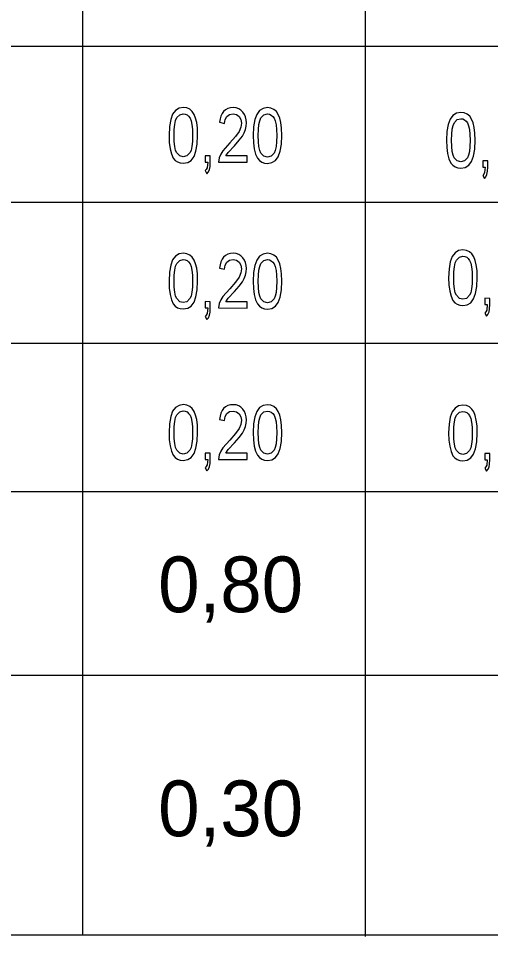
# Model space of a CAD drawing. Extents: x -480568.5 to -480543.1, y -1126945.4 to -1126930.6.
# Drawn here: x -480548.86 to -480548.039, y -1126935.262 to -1126933.667 of the extents above; entities that cross this region are included whole.
import ezdxf

# ---------------------------------------------------------------- set-up
doc = ezdxf.new("R2010")
doc.units = 0
doc.layers.add('detaily', color=7, linetype='Continuous')
doc.layers.add('EL1', color=7, linetype='Continuous')

msp = doc.modelspace()

# ---------------------------------------------------------------- linework, layer by layer
at = {"layer": 'detaily'}
msp.add_lwpolyline([(-480551.8459, -1126935.2592), (-480543.5956, -1126935.2592), (-480543.5956, -1126932.0257), (-480551.8459, -1126932.0257)], close=True, dxfattribs=at)
at = {"layer": 'EL1'}
for p, q in [((-480548.2567, -1126932.0257), (-480548.2567, -1126935.2623)), ((-480548.7479, -1126932.3271), (-480548.7479, -1126935.2592)), ((-480550.8407, -1126933.7155), (-480543.5956, -1126933.7155)), ((-480549.8036, -1126933.9862), (-480543.5956, -1126933.9862)), ((-480550.8351, -1126934.2311), (-480543.5956, -1126934.2311)), ((-480543.5956, -1126934.4894), (-480551.8459, -1126934.4894)), ((-480543.5956, -1126934.8085), (-480551.8459, -1126934.8085))]:
    msp.add_line(p, q, dxfattribs=at)
for points in [[(-480548.5976, -1126933.8705), (-480548.5972, -1126933.883), (-480548.5958, -1126933.8937), (-480548.5935, -1126933.9027), (-480548.5902, -1126933.91), (-480548.5868, -1126933.9139), (-480548.5827, -1126933.9166), (-480548.5781, -1126933.9183), (-480548.5729, -1126933.9189), (-480548.5652, -1126933.9176), (-480548.559, -1126933.9138), (-480548.5542, -1126933.9073), (-480548.5508, -1126933.8979), (-480548.5487, -1126933.8857), (-480548.548, -1126933.8705), (-480548.5484, -1126933.8579), (-480548.5496, -1126933.8481), (-480548.5516, -1126933.8405), (-480548.554, -1126933.834), (-480548.5572, -1126933.8289), (-480548.5616, -1126933.8251), (-480548.5669, -1126933.8228), (-480548.5727, -1126933.822), (-480548.5803, -1126933.8233), (-480548.5865, -1126933.8271), (-480548.5914, -1126933.8337), (-480548.5948, -1126933.8429), (-480548.5969, -1126933.8552)], [(-480548.4617, -1126933.9062), (-480548.4992, -1126933.9062), (-480548.4947, -1126933.9), (-480548.4836, -1126933.8883), (-480548.4755, -1126933.879), (-480548.4702, -1126933.8717), (-480548.4669, -1126933.8658), (-480548.4648, -1126933.8601), (-480548.4635, -1126933.8545), (-480548.4631, -1126933.8488), (-480548.4635, -1126933.8434), (-480548.4646, -1126933.8384), (-480548.4666, -1126933.8339), (-480548.4692, -1126933.8298), (-480548.4726, -1126933.8265), (-480548.4765, -1126933.8241), (-480548.481, -1126933.8226), (-480548.486, -1126933.8222), (-480548.491, -1126933.8226), (-480548.4954, -1126933.8238), (-480548.4993, -1126933.8259), (-480548.5027, -1126933.8287), (-480548.5055, -1126933.8324), (-480548.5076, -1126933.8368), (-480548.509, -1126933.8419), (-480548.5099, -1126933.8477), (-480548.5011, -1126933.8495), (-480548.5001, -1126933.8427), (-480548.497, -1126933.8375), (-480548.4923, -1126933.8342), (-480548.4862, -1126933.8331), (-480548.4804, -1126933.8343), (-480548.4758, -1126933.8378), (-480548.4729, -1126933.843), (-480548.4719, -1126933.8492), (-480548.4729, -1126933.8563), (-480548.4759, -1126933.8634), (-480548.4819, -1126933.8721), (-480548.4918, -1126933.8836), (-480548.5039, -1126933.8971), (-480548.5077, -1126933.903), (-480548.5103, -1126933.9092), (-480548.5114, -1126933.9171), (-480548.4617, -1126933.9172)], [(-480548.4514, -1126933.8706), (-480548.4509, -1126933.8831), (-480548.4495, -1126933.8939), (-480548.4472, -1126933.9029), (-480548.4439, -1126933.9101), (-480548.4405, -1126933.914), (-480548.4364, -1126933.9168), (-480548.4318, -1126933.9185), (-480548.4266, -1126933.919), (-480548.419, -1126933.9178), (-480548.4127, -1126933.9139), (-480548.4079, -1126933.9074), (-480548.4045, -1126933.8981), (-480548.4024, -1126933.8859), (-480548.4017, -1126933.8707), (-480548.4021, -1126933.8581), (-480548.4034, -1126933.8483), (-480548.4053, -1126933.8406), (-480548.4077, -1126933.8342), (-480548.4109, -1126933.8291), (-480548.4153, -1126933.8253), (-480548.4206, -1126933.823), (-480548.4265, -1126933.8222), (-480548.4341, -1126933.8235), (-480548.4403, -1126933.8273), (-480548.4451, -1126933.8339), (-480548.4485, -1126933.8431), (-480548.4507, -1126933.8554)], [(-480548.5889, -1126933.8704), (-480548.5886, -1126933.8601), (-480548.5877, -1126933.8515), (-480548.5862, -1126933.8447), (-480548.5841, -1126933.8396), (-480548.5791, -1126933.8347), (-480548.5729, -1126933.833), (-480548.5694, -1126933.8335), (-480548.5663, -1126933.8349), (-480548.5636, -1126933.8372), (-480548.5611, -1126933.8404), (-480548.5592, -1126933.8451), (-480548.5578, -1126933.8517), (-480548.557, -1126933.8602), (-480548.5567, -1126933.8705), (-480548.557, -1126933.8812), (-480548.5579, -1126933.8898), (-480548.5594, -1126933.8964), (-480548.5614, -1126933.9009), (-480548.5666, -1126933.9062), (-480548.5728, -1126933.9079), (-480548.5791, -1126933.9062), (-480548.5843, -1126933.9009), (-480548.5863, -1126933.8964), (-480548.5878, -1126933.8898), (-480548.5886, -1126933.8812)], [(-480548.4426, -1126933.8706), (-480548.4423, -1126933.8603), (-480548.4414, -1126933.8517), (-480548.4399, -1126933.8449), (-480548.4378, -1126933.8397), (-480548.4328, -1126933.8348), (-480548.4266, -1126933.8332), (-480548.4231, -1126933.8337), (-480548.42, -1126933.8351), (-480548.4173, -1126933.8374), (-480548.4149, -1126933.8406), (-480548.4129, -1126933.8453), (-480548.4115, -1126933.8519), (-480548.4107, -1126933.8603), (-480548.4104, -1126933.8707), (-480548.4107, -1126933.8814), (-480548.4116, -1126933.89), (-480548.4131, -1126933.8966), (-480548.4151, -1126933.9011), (-480548.4203, -1126933.9064), (-480548.4266, -1126933.9081), (-480548.4328, -1126933.9063), (-480548.438, -1126933.9011), (-480548.44, -1126933.8966), (-480548.4415, -1126933.89), (-480548.4423, -1126933.8814)], [(-480548.1153, -1126933.8789), (-480548.1148, -1126933.8914), (-480548.1134, -1126933.9021), (-480548.1111, -1126933.9112), (-480548.1078, -1126933.9184), (-480548.1044, -1126933.9223), (-480548.1003, -1126933.9251), (-480548.0957, -1126933.9267), (-480548.0905, -1126933.9273), (-480548.0829, -1126933.926), (-480548.0766, -1126933.9222), (-480548.0718, -1126933.9157), (-480548.0684, -1126933.9063), (-480548.0663, -1126933.8942), (-480548.0656, -1126933.8789), (-480548.066, -1126933.8663), (-480548.0673, -1126933.8565), (-480548.0692, -1126933.8489), (-480548.0716, -1126933.8424), (-480548.0748, -1126933.8373), (-480548.0792, -1126933.8336), (-480548.0845, -1126933.8312), (-480548.0904, -1126933.8305), (-480548.098, -1126933.8318), (-480548.1042, -1126933.8356), (-480548.109, -1126933.8421), (-480548.1124, -1126933.8514), (-480548.1146, -1126933.8636)], [(-480548.1065, -1126933.8789), (-480548.1062, -1126933.8685), (-480548.1053, -1126933.8599), (-480548.1038, -1126933.8531), (-480548.1017, -1126933.848), (-480548.0967, -1126933.8431), (-480548.0905, -1126933.8414), (-480548.087, -1126933.8419), (-480548.0839, -1126933.8433), (-480548.0812, -1126933.8456), (-480548.0788, -1126933.8489), (-480548.0768, -1126933.8536), (-480548.0754, -1126933.8601), (-480548.0746, -1126933.8686), (-480548.0743, -1126933.8789), (-480548.0746, -1126933.8896), (-480548.0755, -1126933.8982), (-480548.077, -1126933.9048), (-480548.079, -1126933.9093), (-480548.0842, -1126933.9146), (-480548.0905, -1126933.9163), (-480548.0967, -1126933.9146), (-480548.1019, -1126933.9093), (-480548.1039, -1126933.9048), (-480548.1054, -1126933.8982), (-480548.1062, -1126933.8896)], [(-480548.5348, -1126933.9171), (-480548.5304, -1126933.9171), (-480548.5316, -1126933.9267), (-480548.5329, -1126933.9296), (-480548.5348, -1126933.9317), (-480548.5319, -1126933.9372), (-480548.5293, -1126933.934), (-480548.5275, -1126933.9297), (-480548.5264, -1126933.9242), (-480548.526, -1126933.9171), (-480548.526, -1126933.9061), (-480548.5348, -1126933.9061)], [(-480548.0524, -1126933.9255), (-480548.0481, -1126933.9255), (-480548.0492, -1126933.9351), (-480548.0505, -1126933.938), (-480548.0524, -1126933.9401), (-480548.0495, -1126933.9456), (-480548.0469, -1126933.9425), (-480548.0451, -1126933.9382), (-480548.044, -1126933.9326), (-480548.0436, -1126933.9255), (-480548.0436, -1126933.9146), (-480548.0524, -1126933.9146)], [(-480548.5976, -1126934.1236), (-480548.5972, -1126934.1361), (-480548.5958, -1126934.1468), (-480548.5935, -1126934.1558), (-480548.5902, -1126934.1631), (-480548.5868, -1126934.167), (-480548.5827, -1126934.1697), (-480548.5781, -1126934.1714), (-480548.5729, -1126934.172), (-480548.5652, -1126934.1707), (-480548.559, -1126934.1669), (-480548.5542, -1126934.1604), (-480548.5508, -1126934.151), (-480548.5487, -1126934.1388), (-480548.548, -1126934.1236), (-480548.5484, -1126934.111), (-480548.5496, -1126934.1012), (-480548.5516, -1126934.0936), (-480548.554, -1126934.0871), (-480548.5572, -1126934.082), (-480548.5616, -1126934.0783), (-480548.5669, -1126934.0759), (-480548.5727, -1126934.0752), (-480548.5803, -1126934.0764), (-480548.5865, -1126934.0802), (-480548.5914, -1126934.0868), (-480548.5948, -1126934.096), (-480548.5969, -1126934.1083)], [(-480548.4617, -1126934.1593), (-480548.4992, -1126934.1593), (-480548.4947, -1126934.1531), (-480548.4836, -1126934.1414), (-480548.4755, -1126934.1321), (-480548.4702, -1126934.1248), (-480548.4669, -1126934.1189), (-480548.4648, -1126934.1132), (-480548.4635, -1126934.1076), (-480548.4631, -1126934.1019), (-480548.4635, -1126934.0965), (-480548.4646, -1126934.0915), (-480548.4666, -1126934.087), (-480548.4692, -1126934.0829), (-480548.4726, -1126934.0796), (-480548.4765, -1126934.0772), (-480548.481, -1126934.0758), (-480548.486, -1126934.0753), (-480548.491, -1126934.0757), (-480548.4954, -1126934.0769), (-480548.4993, -1126934.079), (-480548.5027, -1126934.0818), (-480548.5055, -1126934.0855), (-480548.5076, -1126934.0899), (-480548.509, -1126934.095), (-480548.5099, -1126934.1008), (-480548.5011, -1126934.1027), (-480548.5001, -1126934.0958), (-480548.497, -1126934.0906), (-480548.4923, -1126934.0873), (-480548.4862, -1126934.0862), (-480548.4804, -1126934.0874), (-480548.4758, -1126934.0909), (-480548.4729, -1126934.0961), (-480548.4719, -1126934.1023), (-480548.4729, -1126934.1094), (-480548.4759, -1126934.1166), (-480548.4819, -1126934.1252), (-480548.4918, -1126934.1367), (-480548.5039, -1126934.1502), (-480548.5077, -1126934.1561), (-480548.5103, -1126934.1623), (-480548.5114, -1126934.1702), (-480548.4617, -1126934.1703)], [(-480548.4514, -1126934.1237), (-480548.4509, -1126934.1363), (-480548.4495, -1126934.147), (-480548.4472, -1126934.156), (-480548.4439, -1126934.1632), (-480548.4405, -1126934.1671), (-480548.4364, -1126934.1699), (-480548.4318, -1126934.1716), (-480548.4266, -1126934.1722), (-480548.419, -1126934.1709), (-480548.4127, -1126934.167), (-480548.4079, -1126934.1605), (-480548.4045, -1126934.1512), (-480548.4024, -1126934.139), (-480548.4017, -1126934.1238), (-480548.4021, -1126934.1112), (-480548.4034, -1126934.1014), (-480548.4053, -1126934.0937), (-480548.4077, -1126934.0873), (-480548.4109, -1126934.0822), (-480548.4153, -1126934.0784), (-480548.4206, -1126934.0761), (-480548.4265, -1126934.0753), (-480548.4341, -1126934.0766), (-480548.4403, -1126934.0804), (-480548.4451, -1126934.087), (-480548.4485, -1126934.0962), (-480548.4507, -1126934.1085)], [(-480548.1116, -1126934.1178), (-480548.1111, -1126934.1303), (-480548.1097, -1126934.141), (-480548.1074, -1126934.15), (-480548.1041, -1126934.1573), (-480548.1007, -1126934.1612), (-480548.0966, -1126934.1639), (-480548.092, -1126934.1656), (-480548.0868, -1126934.1662), (-480548.0792, -1126934.1649), (-480548.0729, -1126934.1611), (-480548.0681, -1126934.1546), (-480548.0647, -1126934.1452), (-480548.0626, -1126934.133), (-480548.0619, -1126934.1178), (-480548.0623, -1126934.1052), (-480548.0636, -1126934.0954), (-480548.0655, -1126934.0878), (-480548.0679, -1126934.0813), (-480548.0711, -1126934.0762), (-480548.0755, -1126934.0725), (-480548.0808, -1126934.0701), (-480548.0867, -1126934.0694), (-480548.0943, -1126934.0706), (-480548.1005, -1126934.0744), (-480548.1053, -1126934.081), (-480548.1087, -1126934.0902), (-480548.1109, -1126934.1025)], [(-480548.1028, -1126934.1177), (-480548.1025, -1126934.1074), (-480548.1016, -1126934.0988), (-480548.1001, -1126934.092), (-480548.098, -1126934.0869), (-480548.093, -1126934.082), (-480548.0868, -1126934.0803), (-480548.0833, -1126934.0808), (-480548.0802, -1126934.0822), (-480548.0775, -1126934.0845), (-480548.0751, -1126934.0877), (-480548.0731, -1126934.0924), (-480548.0717, -1126934.099), (-480548.0709, -1126934.1075), (-480548.0706, -1126934.1178), (-480548.0709, -1126934.1285), (-480548.0718, -1126934.1371), (-480548.0733, -1126934.1437), (-480548.0753, -1126934.1482), (-480548.0805, -1126934.1535), (-480548.0868, -1126934.1552), (-480548.093, -1126934.1535), (-480548.0982, -1126934.1482), (-480548.1002, -1126934.1437), (-480548.1017, -1126934.1371), (-480548.1025, -1126934.1285)], [(-480548.5889, -1126934.1235), (-480548.5886, -1126934.1132), (-480548.5877, -1126934.1046), (-480548.5862, -1126934.0978), (-480548.5841, -1126934.0927), (-480548.5791, -1126934.0878), (-480548.5729, -1126934.0861), (-480548.5694, -1126934.0866), (-480548.5663, -1126934.088), (-480548.5636, -1126934.0903), (-480548.5611, -1126934.0935), (-480548.5592, -1126934.0982), (-480548.5578, -1126934.1048), (-480548.557, -1126934.1133), (-480548.5567, -1126934.1236), (-480548.557, -1126934.1343), (-480548.5579, -1126934.1429), (-480548.5594, -1126934.1495), (-480548.5614, -1126934.154), (-480548.5666, -1126934.1593), (-480548.5728, -1126934.161), (-480548.5791, -1126934.1593), (-480548.5843, -1126934.154), (-480548.5863, -1126934.1495), (-480548.5878, -1126934.1429), (-480548.5886, -1126934.1343)], [(-480548.4426, -1126934.1237), (-480548.4423, -1126934.1134), (-480548.4414, -1126934.1048), (-480548.4399, -1126934.098), (-480548.4378, -1126934.0929), (-480548.4328, -1126934.088), (-480548.4266, -1126934.0863), (-480548.4231, -1126934.0868), (-480548.42, -1126934.0882), (-480548.4173, -1126934.0905), (-480548.4149, -1126934.0937), (-480548.4129, -1126934.0984), (-480548.4115, -1126934.105), (-480548.4107, -1126934.1134), (-480548.4104, -1126934.1238), (-480548.4107, -1126934.1345), (-480548.4116, -1126934.1431), (-480548.4131, -1126934.1497), (-480548.4151, -1126934.1542), (-480548.4203, -1126934.1595), (-480548.4266, -1126934.1612), (-480548.4328, -1126934.1595), (-480548.438, -1126934.1542), (-480548.44, -1126934.1497), (-480548.4415, -1126934.1431), (-480548.4423, -1126934.1345)], [(-480548.5348, -1126934.1702), (-480548.5304, -1126934.1702), (-480548.5316, -1126934.1798), (-480548.5329, -1126934.1827), (-480548.5348, -1126934.1848), (-480548.5319, -1126934.1903), (-480548.5293, -1126934.1871), (-480548.5275, -1126934.1828), (-480548.5264, -1126934.1773), (-480548.526, -1126934.1702), (-480548.526, -1126934.1593), (-480548.5348, -1126934.1592)], [(-480548.0487, -1126934.1644), (-480548.0444, -1126934.1644), (-480548.0455, -1126934.174), (-480548.0468, -1126934.1769), (-480548.0487, -1126934.179), (-480548.0458, -1126934.1845), (-480548.0432, -1126934.1813), (-480548.0414, -1126934.177), (-480548.0403, -1126934.1715), (-480548.0399, -1126934.1644), (-480548.0399, -1126934.1535), (-480548.0487, -1126934.1534)], [(-480548.5976, -1126934.3865), (-480548.5972, -1126934.399), (-480548.5958, -1126934.4098), (-480548.5935, -1126934.4188), (-480548.5902, -1126934.426), (-480548.5868, -1126934.4299), (-480548.5827, -1126934.4327), (-480548.5781, -1126934.4344), (-480548.5729, -1126934.4349), (-480548.5652, -1126934.4337), (-480548.559, -1126934.4298), (-480548.5542, -1126934.4233), (-480548.5508, -1126934.414), (-480548.5487, -1126934.4018), (-480548.548, -1126934.3866), (-480548.5484, -1126934.374), (-480548.5496, -1126934.3642), (-480548.5516, -1126934.3565), (-480548.554, -1126934.3501), (-480548.5572, -1126934.345), (-480548.5616, -1126934.3412), (-480548.5669, -1126934.3389), (-480548.5727, -1126934.3381), (-480548.5803, -1126934.3394), (-480548.5865, -1126934.3432), (-480548.5914, -1126934.3497), (-480548.5948, -1126934.359), (-480548.5969, -1126934.3713)], [(-480548.4617, -1126934.4223), (-480548.4992, -1126934.4223), (-480548.4947, -1126934.4161), (-480548.4836, -1126934.4043), (-480548.4755, -1126934.395), (-480548.4702, -1126934.3878), (-480548.4669, -1126934.3818), (-480548.4648, -1126934.3761), (-480548.4635, -1126934.3705), (-480548.4631, -1126934.3648), (-480548.4635, -1126934.3594), (-480548.4646, -1126934.3545), (-480548.4666, -1126934.35), (-480548.4692, -1126934.3459), (-480548.4726, -1126934.3426), (-480548.4765, -1126934.3402), (-480548.481, -1126934.3387), (-480548.486, -1126934.3382), (-480548.491, -1126934.3386), (-480548.4954, -1126934.3399), (-480548.4993, -1126934.3419), (-480548.5027, -1126934.3448), (-480548.5055, -1126934.3485), (-480548.5076, -1126934.3528), (-480548.509, -1126934.3579), (-480548.5099, -1126934.3638), (-480548.5011, -1126934.3656), (-480548.5001, -1126934.3588), (-480548.497, -1126934.3535), (-480548.4923, -1126934.3503), (-480548.4862, -1126934.3492), (-480548.4804, -1126934.3504), (-480548.4758, -1126934.3539), (-480548.4729, -1126934.3591), (-480548.4719, -1126934.3653), (-480548.4729, -1126934.3724), (-480548.4759, -1126934.3795), (-480548.4819, -1126934.3882), (-480548.4918, -1126934.3997), (-480548.5039, -1126934.4131), (-480548.5077, -1126934.4191), (-480548.5103, -1126934.4253), (-480548.5114, -1126934.4332), (-480548.4617, -1126934.4333)], [(-480548.4514, -1126934.3867), (-480548.4509, -1126934.3992), (-480548.4495, -1126934.41), (-480548.4472, -1126934.419), (-480548.4439, -1126934.4262), (-480548.4405, -1126934.4301), (-480548.4364, -1126934.4329), (-480548.4318, -1126934.4346), (-480548.4266, -1126934.4351), (-480548.419, -1126934.4338), (-480548.4127, -1126934.43), (-480548.4079, -1126934.4235), (-480548.4045, -1126934.4142), (-480548.4024, -1126934.402), (-480548.4017, -1126934.3868), (-480548.4021, -1126934.3741), (-480548.4034, -1126934.3644), (-480548.4053, -1126934.3567), (-480548.4077, -1126934.3503), (-480548.4109, -1126934.3452), (-480548.4153, -1126934.3414), (-480548.4206, -1126934.3391), (-480548.4265, -1126934.3383), (-480548.4341, -1126934.3396), (-480548.4403, -1126934.3434), (-480548.4451, -1126934.3499), (-480548.4485, -1126934.3592), (-480548.4507, -1126934.3714)], [(-480548.1116, -1126934.3873), (-480548.1111, -1126934.3998), (-480548.1097, -1126934.4105), (-480548.1074, -1126934.4196), (-480548.1041, -1126934.4268), (-480548.1007, -1126934.4307), (-480548.0966, -1126934.4335), (-480548.092, -1126934.4352), (-480548.0868, -1126934.4357), (-480548.0792, -1126934.4344), (-480548.0729, -1126934.4306), (-480548.0681, -1126934.4241), (-480548.0647, -1126934.4148), (-480548.0626, -1126934.4026), (-480548.0619, -1126934.3874), (-480548.0623, -1126934.3747), (-480548.0636, -1126934.365), (-480548.0655, -1126934.3573), (-480548.0679, -1126934.3509), (-480548.0711, -1126934.3458), (-480548.0755, -1126934.342), (-480548.0808, -1126934.3397), (-480548.0867, -1126934.3389), (-480548.0943, -1126934.3402), (-480548.1005, -1126934.344), (-480548.1053, -1126934.3505), (-480548.1087, -1126934.3598), (-480548.1109, -1126934.372)], [(-480548.5889, -1126934.3865), (-480548.5886, -1126934.3761), (-480548.5877, -1126934.3676), (-480548.5862, -1126934.3607), (-480548.5841, -1126934.3556), (-480548.5791, -1126934.3507), (-480548.5729, -1126934.3491), (-480548.5694, -1126934.3496), (-480548.5663, -1126934.3509), (-480548.5636, -1126934.3533), (-480548.5611, -1126934.3565), (-480548.5592, -1126934.3612), (-480548.5578, -1126934.3677), (-480548.557, -1126934.3762), (-480548.5567, -1126934.3866), (-480548.557, -1126934.3973), (-480548.5579, -1126934.4059), (-480548.5594, -1126934.4125), (-480548.5614, -1126934.417), (-480548.5666, -1126934.4223), (-480548.5728, -1126934.424), (-480548.5791, -1126934.4222), (-480548.5843, -1126934.417), (-480548.5863, -1126934.4125), (-480548.5878, -1126934.4059), (-480548.5886, -1126934.3972)], [(-480548.4426, -1126934.3867), (-480548.4423, -1126934.3763), (-480548.4414, -1126934.3677), (-480548.4399, -1126934.3609), (-480548.4378, -1126934.3558), (-480548.4328, -1126934.3509), (-480548.4266, -1126934.3493), (-480548.4231, -1126934.3498), (-480548.42, -1126934.3511), (-480548.4173, -1126934.3535), (-480548.4149, -1126934.3567), (-480548.4129, -1126934.3614), (-480548.4115, -1126934.3679), (-480548.4107, -1126934.3764), (-480548.4104, -1126934.3867), (-480548.4107, -1126934.3974), (-480548.4116, -1126934.4061), (-480548.4131, -1126934.4127), (-480548.4151, -1126934.4172), (-480548.4203, -1126934.4224), (-480548.4266, -1126934.4242), (-480548.4328, -1126934.4224), (-480548.438, -1126934.4172), (-480548.44, -1126934.4126), (-480548.4415, -1126934.406), (-480548.4423, -1126934.3974)], [(-480548.1028, -1126934.3873), (-480548.1025, -1126934.3769), (-480548.1016, -1126934.3683), (-480548.1001, -1126934.3615), (-480548.098, -1126934.3564), (-480548.093, -1126934.3515), (-480548.0868, -1126934.3498), (-480548.0833, -1126934.3504), (-480548.0802, -1126934.3517), (-480548.0775, -1126934.3541), (-480548.0751, -1126934.3573), (-480548.0731, -1126934.362), (-480548.0717, -1126934.3685), (-480548.0709, -1126934.377), (-480548.0706, -1126934.3873), (-480548.0709, -1126934.398), (-480548.0718, -1126934.4067), (-480548.0733, -1126934.4132), (-480548.0753, -1126934.4178), (-480548.0805, -1126934.423), (-480548.0868, -1126934.4248), (-480548.093, -1126934.423), (-480548.0982, -1126934.4178), (-480548.1002, -1126934.4132), (-480548.1017, -1126934.4066), (-480548.1025, -1126934.398)], [(-480548.5348, -1126934.4332), (-480548.5304, -1126934.4332), (-480548.5316, -1126934.4428), (-480548.5329, -1126934.4457), (-480548.5348, -1126934.4478), (-480548.5319, -1126934.4533), (-480548.5293, -1126934.4501), (-480548.5275, -1126934.4458), (-480548.5264, -1126934.4402), (-480548.526, -1126934.4332), (-480548.526, -1126934.4222), (-480548.5348, -1126934.4222)], [(-480548.0487, -1126934.4339), (-480548.0444, -1126934.4339), (-480548.0455, -1126934.4435), (-480548.0468, -1126934.4464), (-480548.0487, -1126934.4485), (-480548.0458, -1126934.454), (-480548.0432, -1126934.4509), (-480548.0414, -1126934.4466), (-480548.0403, -1126934.441), (-480548.0399, -1126934.4339), (-480548.0399, -1126934.423), (-480548.0487, -1126934.423)]]:
    msp.add_lwpolyline(points, close=True, dxfattribs=at)

# ---------------------------------------------------------------- texts
for s, rotation, p in [('0,80', 0, (-480548.6166, -1126934.6988)), ('0,30', 360, (-480548.6166, -1126935.0879))]:
    msp.add_text(s, height=0.09683, rotation=rotation, dxfattribs=at).set_placement(p)

doc.saveas('drawing.dxf')
